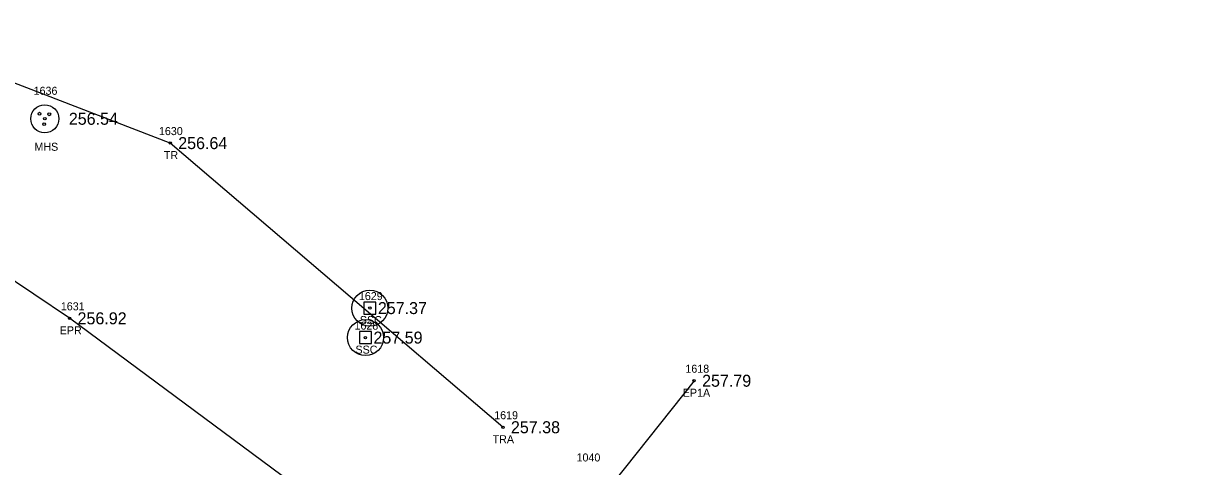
# Model space of a CAD drawing. Extents: x 1961231 to 1962574, y 799865 to 801120.
# Drawn here: x 1961400.7 to 1961547.5, y 801002.7 to 801058.1 of the extents above; entities that cross this region are included whole.
import ezdxf

# ---------------------------------------------------------------- set-up
doc = ezdxf.new("R2010")
doc.units = 0
for name, color, linetype in [('RD_EX_DR_Inlet', 7, 'Continuous'), ('RD_EX_DV_Prop_txCode', 7, 'Continuous'), ('RD_EX_Road', 7, 'Continuous'), ('RD_EX_Road_txCode', 7, 'Continuous'), ('RD_EX_TX_Road_ELEV', 7, 'Continuous'), ('RD_EX_TX_UT_ELEV', 7, 'Continuous'), ('RD_EX_TX_VEG_ELEV', 7, 'Continuous'), ('RD_EX_UT', 7, 'Continuous'), ('RD_EX_UT_txCode', 7, 'Continuous'), ('RD_EX_VEG', 7, 'Continuous'), ('RD_EX_VEG_txCode', 7, 'Continuous'), ('RD_SMD_Locator', 7, 'Continuous')]:
    doc.layers.add(name, color=color, linetype=linetype)

msp = doc.modelspace()

# ---------------------------------------------------------------- linework, layer by layer
at = {"layer": 'RD_EX_DR_Inlet'}
for centre, radius in [((1961403.32, 801046.17), 1.75), ((1961402.65, 801046.8), 0.175), ((1961403.88, 801046.73), 0.175), ((1961403.23, 801045.5), 0.175)]:
    msp.add_circle(centre, radius, dxfattribs=at)
at = {"layer": 'RD_EX_Road'}
for points in [[(1961735.63, 800762.82), (1961702.92, 800788.52), (1961676.16, 800810.27), (1961651.45, 800830.73), (1961641.14, 800839.02), (1961595.18, 800874.45), (1961552.9, 800907.54), (1961510.92, 800940.49), (1961504.01, 800946.58), (1961476.53, 800968.16), (1961444.88, 800992.72), (1961406.41, 801021.23), (1961370.69, 801045.26)], [(1961484.46, 801013.43), (1961472.97, 800998.95), (1961472.49, 800999.38), (1961464.24, 800989.69), (1961459.67, 800987.19), (1961451.78, 800987.58)]]:
    msp.add_lwpolyline(points, dxfattribs=at)
at = {"layer": 'RD_EX_UT'}
for p, q in [((1961444.69, 801023.26), (1961443.19, 801023.26)), ((1961443.19, 801023.26), (1961443.19, 801021.76)), ((1961444.69, 801021.76), (1961444.69, 801023.26)), ((1961443.19, 801021.76), (1961444.69, 801021.76)), ((1961444.14, 801019.57), (1961442.64, 801019.57)), ((1961442.64, 801019.57), (1961442.64, 801018.07)), ((1961444.14, 801018.07), (1961444.14, 801019.57)), ((1961442.64, 801018.07), (1961444.14, 801018.07))]:
    msp.add_line(p, q, dxfattribs=at)
for centre in [(1961443.94, 801022.51), (1961443.39, 801018.82)]:
    msp.add_circle(centre, 2.25, dxfattribs=at)
at = {"layer": 'RD_EX_VEG'}
msp.add_lwpolyline([(1961460.57, 801007.62), (1961418.99, 801043.13), (1961380.21, 801058.08)], dxfattribs=at)
at = {"layer": 'RD_SMD_Locator'}
for centre in [(1961403.32, 801046.17), (1961418.99, 801043.13), (1961443.94, 801022.51), (1961406.41, 801021.23), (1961443.39, 801018.82), (1961484.46, 801013.43), (1961460.57, 801007.62)]:
    msp.add_circle(centre, 0.15, dxfattribs=at)

# ---------------------------------------------------------------- texts
at = {"layer": 'RD_EX_DV_Prop_txCode'}
msp.add_text('1040', height=1, dxfattribs=at).set_placement((1961469.77, 801003.34))
at = {"layer": 'RD_EX_Road_txCode'}
for s, p in [('1631', (1961405.32, 801022.23)), ('EPR', (1961405.18, 801019.23)), ('1618', (1961483.37, 801014.43)), ('EP1A', (1961483.05, 801011.43))]:
    msp.add_text(s, height=1, dxfattribs=at).set_placement(p)
at = {"layer": 'RD_EX_TX_Road_ELEV'}
for s, p in [('256.92', (1961407.41, 801020.48)), ('257.79', (1961485.46, 801012.68))]:
    msp.add_text(s, height=1.5, dxfattribs=at).set_placement(p)
at = {"layer": 'RD_EX_TX_UT_ELEV'}
for s, p in [('256.54', (1961406.32, 801045.42)), ('257.37', (1961444.94, 801021.76)), ('257.59', (1961444.39, 801018.07))]:
    msp.add_text(s, height=1.5, dxfattribs=at).set_placement(p)
at = {"layer": 'RD_EX_TX_VEG_ELEV'}
for s, p in [('256.64', (1961419.99, 801042.38)), ('257.38', (1961461.57, 801006.87))]:
    msp.add_text(s, height=1.5, dxfattribs=at).set_placement(p)
at = {"layer": 'RD_EX_UT_txCode'}
for s, p in [('1636', (1961401.92, 801049.17)), ('MHS', (1961402.02, 801042.17)), ('1629', (1961442.57, 801023.51)), ('1628', (1961442.02, 801019.82)), ('SSC', (1961442.69, 801020.51)), ('SSC', (1961442.14, 801016.82))]:
    msp.add_text(s, height=1, dxfattribs=at).set_placement(p)
at = {"layer": 'RD_EX_VEG_txCode'}
for s, p in [('1630', (1961417.58, 801044.13)), ('TR', (1961418.19, 801041.13)), ('1619', (1961459.48, 801008.62)), ('TRA', (1961459.28, 801005.62))]:
    msp.add_text(s, height=1, dxfattribs=at).set_placement(p)

doc.saveas('drawing.dxf')
